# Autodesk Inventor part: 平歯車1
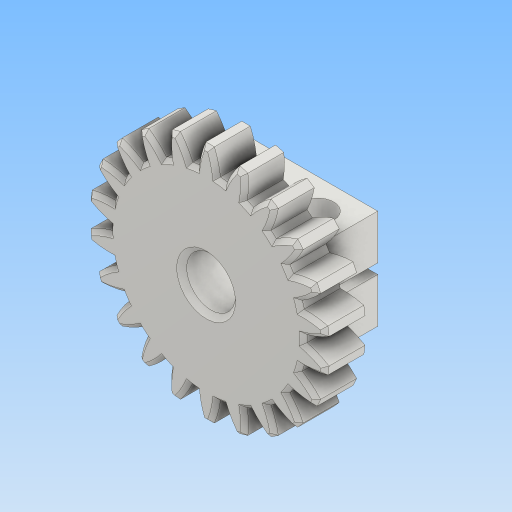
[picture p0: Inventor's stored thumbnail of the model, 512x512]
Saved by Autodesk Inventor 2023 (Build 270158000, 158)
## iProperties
CustomPartVersion: 1
Created: 2024-01
Part Number: 平歯車1
Material: Steel
Document SubType Name: Modeling
Designer: kumagai
Categories: <?xml version="1.0" encoding="UTF-16"?> <MemberInstance><Categories><FamilyTemplate><FamilyTemplateParameter ValueType="xs:double" Id="1" ObjectReferenceKey="da
Density: 1 g/cm^3
Appearance: Steel
Author: kumagai
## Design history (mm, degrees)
sketch "Sketch1"
  geometry: C1 r 12 at (0, 0); C2 r 2.45 at (0, 0); 1 further point
  constraints: 2 centre point, 2 coincident
  dimensions: "d0" = 24 diameter of C1 (= da_da); "d49" = 4.9 diameter of C2
extrude "Extrusion1" new body sketch "Sketch1" distance "d1" = 4 (= da_b); taper "d2" = 0 deg
workplane "Work Plane2"
sketch "Sketch2"
  geometry: C1 r 12 at (0, 0) reference; C2 r 11 at (0, 0)
  constraints: 1 centre point, 1 coincident
  dimensions: "d3" = 22 diameter of C2 (= da_d)
feature "ピッチ円直径" sketch "Sketch2" dims "d4" = 10, "d5" = 0
workplane "Work Plane8"
workplane "Work Plane9"
feature "平歯車" dims "da_b" = 4, "da_d" = 22, "da_aw" = 22, "da_da" = 24, "da_df" = 19.5, "da_dw" = 22, angle "da_beta" = 0 deg, "da_lefttooth" = 0, "da_righttooth" = 0
sketch "スケッチ3"
  geometry: L1 (0, 3.94)-(0, -6.49) reference; L2 (-10.08, 0)-(10.08, 0) reference; L3 (-7.2, -0.5)-(7.2, -0.5); L4 (7.2, -0.5)-(7.2, -5); L5 (7.2, -5)-(-7.2, -5); L6 (-7.2, -5)-(-7.2, -0.5); C1 r 2.45 at (0, 0); 3 further points
  constraints: 8 end point, 1 centre point, 1 coincident, 1 other
  dimensions: "d54" = 0.5 distance between parallel lines of L2 L3; "d55" = 7.2 distance between parallel lines of L6 L1; "d56" = 5 distance between parallel lines of L2 L5; "d59" = 4.9 diameter of C1
extrude "押し出し2" join sketch "スケッチ3" distance "d57" = 6; taper "d58" = 0 deg
sketch "スケッチ4"
  geometry: L1 (0, -5.52)-(0, 0.92) reference; L2 (-8.12, 0)-(8.12, 0) reference; C1 r 1.6 at (4.2, -3); C2 r 1.6 at (-4.2, -3); 1 further point
  constraints: 2 centre point, 1 other
  dimensions: "d60" = 3.2 diameter of C1; "d61" = 3 distance from line of L2 C1.centre; "d62" = 4.2 distance from line of L1 C1.centre
extrude "押し出し3" cut sketch "スケッチ4" extent not by distance; stored distance "d63" = 0; taper "d64" = 0 deg
pattern_circular "円形状パターン1" dims angle "d66" = 360 deg
chamfer "面取り2" distance "d68" = 0.5; stored, may be unused: second distance "d69" = 2, angle "d70" = 45 deg
chamfer "面取り3" distance "d81" = 0.4; stored, may be unused: second distance "d82" = 2, angle "d83" = 45 deg
body "Solid1"
body "Srf1"
other parameters: "d16" = 22 (= da_aw), "d17" = 0, "d34" = 1.428 (computed from da_z), "d39" = 0, "d41" = 0, "d43" = 22 (= da_aw), "d46" = 22 (= da_aw), "d47" = 0, "d48" = 0
